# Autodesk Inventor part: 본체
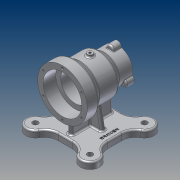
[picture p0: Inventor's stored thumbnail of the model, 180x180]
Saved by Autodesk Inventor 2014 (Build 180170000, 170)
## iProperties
Created: 2017-03
Part Number: 본체
Material: 알루미늄 6061
Document SubType Name: Modeling
Designer: Administrator
Density: 2.71 g/cm^3
Appearance: 알루미늄 - 평지
Mass: 997.337 g
Surface Area: 848.351 cm^2
Volume: 368.021 cm^3
Author: Administrator
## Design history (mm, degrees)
sketch "스케치1"
  geometry: L1 (-50, 0)-(50, 0); L2 (-50, 35)-(-50, 45); L3 (-50, 45)-(-30, 45); L4 (-30, 45)-(-19, 36); L5 (-19, 36)-(15, 36); L6 (15, 36)-(25.389, 27.5); L7 (25.389, 27.5)-(50, 27.5); L8 (50, 27.5)-(50, 17.5); L9 (50, 17.5)-(20, 17.5); L10 (20, 17.5)-(20, 26); L11 (20, 26)-(-27, 26); L12 (-27, 26)-(-27, 35); L13 (-27, 35)-(-50, 35); 2 further points
  constraints: 26 end point, 7 parallel, 2 horizontal, 2 perpendicular, 2 point on line, 1 coincident, 1 midpoint, 1 vertical
  dimensions: "d0" = 100 distance of L1.start L1.end; "d1" = 70 diameter of L13 L1; "d4" = 90 diameter of L3 L1; "d5" = 52 diameter of L11 L1; "d6" = 35 diameter of L9 L1; "d7" = 23 distance between parallel lines of L12 L2; "d9" = 72 diameter of L5 L1; "d10" = 55 diameter of L7 L1; "d11" = 20 distance from line of L3.end L2; "d12" = 31 distance from line of L2 L4.end; "d13" = 65 distance from line of L2 L5.end; "d15" = 30 distance between parallel lines of L10 L8; "d16" = 47 distance between parallel lines of L12 L10 (derived)
revolve "회전1" sketch "스케치1" stored, may be unused: angle "d17" = 90 deg
node "작업 평면1"
sketch "스케치2"
  geometry: L1 (-45, 45)-(45, 45); L2 (45, 45)-(45, -45); L3 (45, -45)-(-45, -45); L4 (-45, -45)-(-45, 45); L5 (-45, 45)-(45, -45); L6 (45, 45)-(-45, -45); L7 (0, 0)-(70, 0)
  constraints: 14 end point, 2 horizontal, 2 midpoint, 2 parallel, 1 perpendicular
  dimensions: "d19" = 90 distance of L2.end L3.end; "d20" = 90 distance of L1.end L2.end
extrude "돌출1" join sketch "스케치2" distance "d25" = 12; taper "d26" = 0 deg
sketch "스케치3"
  geometry: L1 (0, 0)-(-49.497, 49.497); L2 (0, 0)-(70, 0); L3 (-49.497, 49.497)-(-50.837, 50.837); L4 (-45, -45)-(-45, 45) reference; L5 (-45, 45)-(45, 45) reference; L6 (0, 0)-(49.497, 49.497); L7 (0, 0)-(70, 0); L8 (45, 45)-(45, -45) reference; L9 (0, 0)-(49.497, -49.497); L10 (45, -45)-(-45, -45) reference; L11 (45, -12.842)-(45, -45); L12 (12.842, -45)-(45, -45); A1 r 17 centre (49.497, 49.497) between (57.796, 34.661) and (34.661, 57.796); A2 r 25 centre (70, 12.842) between (57.796, 34.661) and (45, 12.842); A3 r 25 centre (12.842, 70) between (12.842, 45) and (34.661, 57.796); A4 r 17 centre (49.497, -49.497) between (57.796, -34.661) and (34.661, -57.796); A5 r 25 centre (70, -12.842) between (45, -12.842) and (57.796, -34.661); A6 r 25 centre (12.842, -70) between (34.661, -57.796) and (12.842, -45); 2 further points
  constraints: 17 end point, 12 point on circle, 9 tangent, 6 centre point, 3 coincident, 3 collinear, 3 point on line, 2 equal length, 2 horizontal, 2 perpendicular
  dimensions: "d28" = 70 distance of L1.start L1.end; "d29" = 135 deg angle of L2 L1; "d39" = 70 distance of L6.end L1.start; "d40" = 45 deg angle of L7 L6 (derived); "d41" = 34 diameter of A1; "d42" = 25 radius of A2; "d43" = 25 radius of A3; "d54" = 70 distance of L1.start L9.end; "d55" = 34 diameter of A4; "d56" = 25 radius of A5; "d57" = 25 radius of A6
extrude "돌출2" join sketch "스케치3" distance "d44" = 12; taper "d45" = 0 deg
hole "구멍1" sketch "스케치3" diameter "d46" = 10; stored, may be unused: countersink angle "d50" = 90 deg, drill point angle "d52" = 118 deg; dims "d47" = 6, "d48" = 4, "d49" = 2, "d51" = 8
hole "구멍2" diameter "d60" = 10; stored, may be unused: countersink angle "d64" = 90 deg, drill point angle "d66" = 118 deg; dims "d58" = 10, "d59" = 10, "d61" = 6, "d62" = 4, "d63" = 2, "d65" = 8
sketch "스케치5"
  geometry: L1 (-31.096, 18.14)-(-70, 25); L2 (-31.096, -18.14)-(-70, -25); L3 (-70, -34.661)-(-70, -12.842) reference; L4 (-70, 12.842)-(-70, 34.661) reference; L5 (-70, -34.661)-(-70, -66.497) reference; L6 (-70, 66.497)-(-70, 34.661) reference; L7 (-70, -12.842)-(-70, 12.842) reference; A1 r 36 centre (0, 0) between (-31.096, 18.14) and (-31.096, -18.14) reference; 3 further points
  constraints: 4 end point, 2 point on circle, 2 point on line
  dimensions: "d68" = 25 vertical distance of point (0, 0) L1.end; "d69" = 25 vertical distance of L2.end point (0, 0); "d70" = 100 deg angle of L5 L2; "d71" = 100 deg angle of L1 L6
extrude "돌출3" join sketch "스케치5" stored distance "d72" = 8; taper "d73" = 0 deg
sketch "스케치6"
  geometry: L1 (-19, -36)-(15, -36) reference; L2 (25.389, -27.5)-(50, -27.5) reference; L3 (15, -36)-(25.389, -27.5) reference; L4 (-30, -45)-(-19, -36) reference; L5 (-50, -45)-(-30, -45) reference; L6 (-12.842, -70)-(-34.661, -70) reference; L7 (12.842, -70)-(34.661, -70) reference; L8 (-66.497, -70)-(-34.661, -70) reference; L9 (66.497, -70)-(34.661, -70) reference; L10 (-37, -45)-(-37, -70); L11 (37, -70)-(37, -27.5); 3 further points
  constraints: 4 end point, 4 point on line, 1 parallel, 1 perpendicular
  dimensions: "d74" = 37 distance from line of point (0, 0) L10; "d75" = 37 distance from line of L11 point (0, 0)
feature "리브1" dims "d76" = 1, "d77" = 8, "d78" = 0, "d79" = 0, "d80" = 1, "d81" = 1
feature "리브2" dims "d82" = 1, "d83" = 8, "d84" = 0, "d85" = 0, "d86" = 1, "d87" = 1
sketch "스케치7"
  geometry: L1 (0, 0)-(0, 40); 1 further point
  constraints: 2 end point, 1 coincident, 1 vertical
  dimensions: "d88" = 40 distance of L1.start L1.end
hole "구멍3" sketch "스케치7" at (0, 40) diameter "d89" = 3.242; stored, may be unused: countersink angle "d93" = 90 deg, drill point angle "d95" = 118 deg; dims "d90" = 9, "d91" = 4, "d92" = 2, "d94" = 11
sketch "스케치8"
  geometry: A1 r 7 centre (0, 27.5) between (6.943, 26.609) and (-6.943, 26.609); A2 r 27.5 centre (0, 0) between (-6.943, 26.609) and (6.943, 26.609) reference; 1 further point
  constraints: 4 point on circle, 1 centre point, 1 vertical alignment
  dimensions: "d99" = 14 diameter of A1; "d100" = 27.5 distance of point (0, 0) A1.centre
extrude "돌출4" join sketch "스케치8" distance "d101" = 15; taper "d102" = 0 deg
hole "구멍4" diameter "d105" = 3.242; stored, may be unused: countersink angle "d109" = 90 deg, drill point angle "d111" = 118 deg; dims "d103" = 10, "d104" = 10, "d106" = 9, "d107" = 4, "d108" = 2, "d110" = 11
fillet "모깎기1" dims "d115" = 3
fillet "모깎기2" dims "d116" = 1
node "작업 평면2"
sketch "스케치9"
  geometry: C1 r 5 at (0, 0); 1 further point
  constraints: 1 centre point, 1 coincident
  dimensions: "d118" = 10 diameter of C1
extrude "돌출5" join sketch "스케치9" stored distance "d119" = 15; taper "d120" = 0 deg
hole "구멍5" diameter "d123" = 4.134; stored, may be unused: countersink angle "d127" = 90 deg, drill point angle "d129" = 118 deg; dims "d121" = 10, "d122" = 10, "d124" = 9, "d125" = 4, "d126" = 2, "d128" = 11
fillet "모깎기3" dims "d130" = 3
fillet "모깎기4" dims "d131" = 3
fillet "모깎기5" dims "d132" = 3
fillet "모깎기6" dims "d133" = 3
chamfer "모따기1" distance "d134" = 1; stored, may be unused: second distance "d135" = 2, angle "d136" = 45 deg
fillet "모깎기7" dims "d137" = 3
node "작업 평면3"
sketch "스케치10"
  geometry: 2 further points
  constraints: 1 vertical alignment, 1 other
  dimensions: "d139" = 35 distance of point (0, 0) point (0, -35)
feature "엠보싱1" sketch "스케치10" dims "d0" = 100, "d19" = 90, "d20" = 90, "d140" = 0.5, "d141" = 0
node "솔리드1"
mirror "대칭1"
pattern_circular "원형 패턴1" dims angle "d97" = 360 deg
pattern_circular "원형 패턴2" dims angle "d113" = 360 deg
other parameters: "d18" = -82
